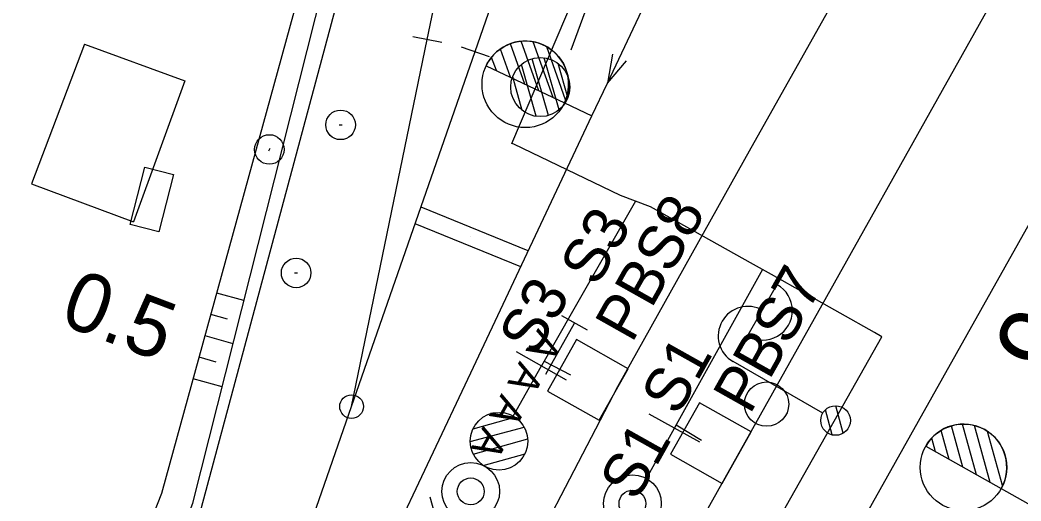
# Model space of a CAD drawing. Extents: x -781083 to -763634, y -1029516 to -1022695.
# Drawn here: x -765207.99 to -765174.13, y -1024229.83 to -1024213.57 of the extents above; entities that cross this region are included whole.
import ezdxf

# ---------------------------------------------------------------- set-up
doc = ezdxf.new("R2010")
doc.units = 0
for name, color, linetype in [('Default', 7, 'Continuous'), ('PS_12-01-10_Kabelizace_nove_kabelizace', 7, 'Continuous'), ('PS_12-01-11_SZZ_Slany_nove_prvky', 7, 'Continuous'), ('PS_12-01-11_SZZ_Slany_nove_prvky_popis', 7, 'Continuous'), ('PS_12-01-11_SZZ_Slany_rusene_prvky', 7, 'Continuous'), ('PS_12-01-11_SZZ_Slany_rusene_prvky_popis', 7, 'Continuous'), ('Vnitřní kresba', 7, 'Continuous'), ('Vrstva 1', 7, 'Continuous'), ('Vrstva 2', 7, 'Continuous'), ('Vrstva 25', 7, 'Continuous'), ('Vrstva 28', 7, 'Continuous'), ('Vrstva 48', 7, 'Continuous'), ('Vrstva 49', 7, 'Continuous'), ('Vrstva 7', 7, 'Continuous')]:
    doc.layers.add(name, color=color, linetype=linetype)

# ---------------------------------------------------------------- blocks, each defined once
blk = doc.blocks.new('C669')
at = {"layer": 'Vrstva 25'}
for p, q in [((0, 5), (0, 40)), ((7, 40), (33, 40)), ((-4.78, -1.46), (1.44, 4.76)), ((-2.39, -4.37), (4.38, 2.4))]:
    blk.add_line(p, q, dxfattribs=at)
blk.add_circle((0, 0), 5, dxfattribs=at)
for centre, start, end in [((10, 40), 0, 180), ((20, 39.88), 179.2974, 0.7026)]:
    blk.add_arc(centre, 10, start, end, dxfattribs=at)
blk = doc.blocks.new('C202')
at = {"layer": 'Vrstva 25'}
blk.add_lwpolyline([(-10, -5), (-10, 5), (10, 5), (10, -5), (-10, -5)], dxfattribs=at)
blk = doc.blocks.new('C053_2')
at = {"layer": 'Vrstva 25'}
blk.add_line((-0.5, 0), (0.5, 0), dxfattribs=at)
blk.add_circle((0, 0), 5, dxfattribs=at)
blk = doc.blocks.new('C093_3')
at = {"layer": 'Vrstva 7'}
blk.add_line((-0.5, 0), (0.5, 0), dxfattribs=at)
blk.add_circle((0, 0), 5, dxfattribs=at)
blk = doc.blocks.new('C321')
at = {"layer": 'Vrstva 2'}
blk.add_lwpolyline([(9.66, 2.59), (0, 0), (9.66, -2.59)], dxfattribs=at)
blk = doc.blocks.new('C084_2')
at = {"layer": 'Vrstva 2'}
blk.add_line((0, 5), (0, -5), dxfattribs=at)
blk = doc.blocks.new('C083_1')
at = {"layer": 'Vrstva 2'}
blk.add_circle((0, 0), 4, dxfattribs=at)
blk = doc.blocks.new('C515_2')
at = {"layer": 'Vrstva 2'}
for p, q in [((-0.02, 35.76), (3.35, 39.13)), ((-0.02, 30.45), (7.16, 37.63)), ((-0.02, 25.15), (10.19, 35.36)), ((-0.03, 19.84), (12.53, 32.4)), ((-0.03, 14.54), (14.1, 28.67)), ((1.1, 10.37), (14.53, 23.79)), ((0, 10.29), (0, 0))]:
    blk.add_line(p, q, dxfattribs=at)
blk.add_lwpolyline([(0, 39.56), (0, 10.29)], dxfattribs=at)
blk.add_circle((0, 24.93), 14.64, dxfattribs=at)
blk.add_arc((0, 24.93), 14.63, 270.0191, 89.98, dxfattribs=at)
blk = doc.blocks.new('C515_4')
at = {"layer": 'Vrstva 2'}
for p, q in [((-0.02, 35.76), (3.35, 39.13)), ((-0.02, 30.45), (7.16, 37.63)), ((-0.02, 25.15), (10.19, 35.36)), ((-0.03, 19.84), (12.53, 32.4)), ((-0.03, 14.54), (14.1, 28.67)), ((1.1, 10.37), (14.53, 23.79)), ((0, 10.29), (0, 0))]:
    blk.add_line(p, q, dxfattribs=at)
blk.add_lwpolyline([(0, 39.56), (0, 10.29)], dxfattribs=at)
blk.add_circle((0, 24.92), 14.64, dxfattribs=at)
blk.add_arc((0, 24.92), 14.63, 270.0191, 89.98, dxfattribs=at)
blk = doc.blocks.new('POINT_DISPLAY')
at = {"layer": 'Default'}
blk.add_line((0, 0), (0, 0), dxfattribs=at)
blk = doc.blocks.new('C335')
at = {"layer": 'Vrstva 7'}
blk.add_blockref('POINT_DISPLAY', (0, 0), dxfattribs=at)
blk = doc.blocks.new('C513_20')
at = {"layer": 'Vrstva 7'}
blk.add_circle((0, 0), 7.5, dxfattribs=at)
blk = doc.blocks.new('C016_8')
at = {"layer": 'PS_12-01-11_SZZ_Slany_rusene_prvky'}
for p, q in [((0, 5), (0, -5)), ((19.8, 0), (0, 0))]:
    blk.add_line(p, q, dxfattribs=at)
blk = doc.blocks.new('SB11_6')
at = {"layer": 'PS_12-01-11_SZZ_Slany_nove_prvky'}
blk.add_lwpolyline([(-125.2, 185.1), (-223.2, 11.3), (-49, -86.9), (49, 86.9)], close=True, dxfattribs=at)
blk = doc.blocks.new('NS12_1')
at = {"layer": 'PS_12-01-11_SZZ_Slany_nove_prvky'}
for p, q in [((-10.61, 115.61), (-17, 122)), ((-14.95, 104.3), (0.71, 119.96)), ((10.61, 115.61), (17, 122)), ((-14.06, 99.88), (5.12, 119.06)), ((-13.82, 110.73), (-5.7, 118.86)), ((-12.24, 96.4), (8.61, 117.25)), ((-9.72, 93.62), (11.4, 114.74)), ((-6.52, 91.51), (13.48, 111.52)), ((-2.5, 90.23), (14.77, 107.5)), ((2.88, 90.31), (14.72, 102.15)), ((-10.61, 94.39), (-17, 88)), ((10.61, 94.39), (17, 88)), ((0.97, 59.97), (-14.97, 44.03)), ((8.42, 57.42), (-12.42, 36.58)), ((12.99, 52.49), (-7.8, 32.19)), ((14.97, 45.97), (-1, 30)), ((0, 30), (0, 0)), ((-15, 0), (15, 0))]:
    blk.add_line(p, q, dxfattribs=at)
for centre, radius in [((0, 135), 15), ((0, 105), 15), ((0, 75), 15), ((0, 75), 7), ((0, 45), 15)]:
    blk.add_circle(centre, radius, dxfattribs=at)
blk = doc.blocks.new('NS8')
at = {"layer": 'PS_12-01-11_SZZ_Slany_nove_prvky'}
for p, q in [((-10.61, 85.61), (-17, 92)), ((-14.92, 73.72), (1.27, 89.91)), ((-14.24, 79.71), (-4.75, 89.19)), ((-13.91, 69.42), (5.56, 88.89)), ((10.61, 85.61), (17, 92)), ((-11.99, 66.04), (8.96, 86.99)), ((-9.38, 63.35), (11.66, 84.39)), ((-6.1, 61.33), (13.69, 81.12)), ((-1.96, 60.16), (14.86, 76.98)), ((3.63, 60.45), (14.51, 71.33)), ((-10.61, 64.39), (-17, 58)), ((10.61, 64.39), (17, 58)), ((0, 30), (0, 0)), ((-15, 0), (15, 0))]:
    blk.add_line(p, q, dxfattribs=at)
for centre, radius in [((0, 105), 15), ((0, 75), 15), ((0, 45), 15), ((0, 45), 7)]:
    blk.add_circle(centre, radius, dxfattribs=at)
blk = doc.blocks.new('PZ2_2')
at = {"layer": 'PS_12-01-11_SZZ_Slany_nove_prvky'}
for p, q in [((-18.83, -0.14), (-23.82, 17.41)), ((-14.74, 0.11), (-20.2, 19.3)), ((-11.12, 2.04), (-16.13, 19.62)), ((-8.14, 6.18), (-11.41, 17.64)), ((-23.54, 1.82), (-26.79, 13.24))]:
    blk.add_line(p, q, dxfattribs=at)
blk.add_circle((-17.47, 9.73), 10, dxfattribs=at)

msp = doc.modelspace()

# ---------------------------------------------------------------- linework, layer by layer
at = {"layer": 'PS_12-01-10_Kabelizace_nove_kabelizace'}
for p, q in [((-765187.174, -1024219.69), (-765190.349, -1024225.261)), ((-765182.877, -1024222.007), (-765185.855, -1024227.362)), ((-765190.256, -1024225.098), (-765189.37, -1024225.561)), ((-765185.793, -1024227.252), (-765184.938, -1024227.77))]:
    msp.add_line(p, q, dxfattribs=at)
msp.add_lwpolyline([(-765187.778, -1024240.091), (-765178.835, -1024224.275), (-765179.085, -1024224.133), (-765182.574, -1024222.177), (-765183.179, -1024221.837), (-765186.668, -1024219.881), (-765187.68, -1024219.499), (-765191.287, -1024217.769), (-765191.359, -1024217.739), (-765182.417, -1024196.766), (-765166.811, -1024163.482)], dxfattribs=at)
at = {"layer": 'Vnitřní kresba'}
for p, q in [((-765205.81, -1024214.38), (-765207.6, -1024219.11)), ((-765205.81, -1024214.38), (-765202.41, -1024215.62)), ((-765202.41, -1024215.62), (-765204.15, -1024220.39)), ((-765207.6, -1024219.11), (-765204.15, -1024220.39))]:
    msp.add_line(p, q, dxfattribs=at)
at = {"layer": 'Vrstva 1'}
for points in [[(-765188.123, -1024215.705), (-765183.275, -1024205.436), (-765176.4, -1024194.792), (-765173.261, -1024189.785), (-765169.195, -1024182.942), (-765164.586, -1024174.885), (-765158.873, -1024164.755), (-765150.27, -1024149.435), (-765143.977, -1024138.227), (-765137.411, -1024126.534), (-765129.538, -1024112.519), (-765123.879, -1024102.438), (-765115.14, -1024086.868), (-765106.342, -1024071.201), (-765098.535, -1024057.295), (-765090.39, -1024042.796), (-765081.493, -1024026.948), (-765072.655, -1024011.193), (-765066.823, -1024000.8), (-765059.521, -1023987.798)], [(-765188.645, -1024216.807), (-765188.123, -1024215.705), (-765183.275, -1024205.436), (-765177.884, -1024194.018), (-765175.294, -1024188.539), (-765171.011, -1024179.395), (-765166.902, -1024170.85), (-765161.865, -1024161.015), (-765157.64, -1024153.172), (-765153.216, -1024145.159), (-765145.723, -1024131.826), (-765138.513, -1024118.992), (-765134.338, -1024111.53), (-765125.127, -1024095.069), (-765118.846, -1024083.871), (-765111.182, -1024070.221), (-765102.382, -1024054.5), (-765092.788, -1024037.408), (-765084.151, -1024022.024), (-765076.991, -1024009.249), (-765068.63, -1023994.356)], [(-765215.522, -1024287.533), (-765214.869, -1024286.147), (-765208.592, -1024272.488), (-765202.041, -1024257.278), (-765199.225, -1024250.55), (-765195.719, -1024242.277), (-765191.973, -1024234.063), (-765191.905, -1024233.922), (-765187.773, -1024225.954), (-765183.261, -1024217.887), (-765177.292, -1024207.279), (-765170.878, -1024195.834), (-765163.532, -1024182.764), (-765155.727, -1024168.863), (-765148.415, -1024155.812), (-765140.866, -1024142.346)], [(-765200.909, -1024238.522), (-765200.512, -1024237.363), (-765196.775, -1024226.639), (-765194.217, -1024214.221), (-765192.75, -1024207.206), (-765190.136, -1024194.92), (-765187.944, -1024184.628), (-765186.685, -1024178.691), (-765184.006, -1024166.028), (-765181.702, -1024155.329), (-765179.632, -1024145.998)], [(-765208.592, -1024272.488), (-765200.394, -1024258.001), (-765194.324, -1024247.14), (-765187.882, -1024235.72), (-765182.524, -1024226.176), (-765175.117, -1024212.969), (-765167.745, -1024199.837), (-765160.378, -1024186.68), (-765154.91, -1024176.911), (-765146.757, -1024162.404), (-765139.177, -1024148.91)], [(-765227.172, -1024323.332), (-765226.383, -1024321.987), (-765218.823, -1024308.994), (-765212.016, -1024293.682), (-765210.286, -1024289.72), (-765207.837, -1024284.198), (-765203.542, -1024274.997), (-765199.177, -1024266.185), (-765195.745, -1024259.62), (-765191.959, -1024252.744), (-765183.924, -1024238.408), (-765177.594, -1024227.134), (-765171.735, -1024216.696), (-765164.143, -1024203.205), (-765156.397, -1024189.358), (-765149.423, -1024176.961), (-765143.434, -1024166.31), (-765138.578, -1024157.675), (-765133.719, -1024149)], [(-765192.593, -1024214.636), (-765189.514, -1024205.768), (-765186.319, -1024196.582), (-765184.058, -1024190.088)], [(-765200.909, -1024238.522), (-765200.512, -1024237.363), (-765196.775, -1024226.639), (-765192.593, -1024214.636)], [(-765211.766, -1024269.927), (-765211.276, -1024268.47), (-765206.854, -1024255.717), (-765199.221, -1024239.235), (-765196.829, -1024234.152), (-765192.736, -1024225.492), (-765188.645, -1024216.807)]]:
    msp.add_lwpolyline(points, dxfattribs=at)
at = {"layer": 'Vrstva 2'}
msp.add_line((-765196.775, -1024226.639), (-765194.217, -1024214.221), dxfattribs=at)
for points in [[(-765188.645, -1024216.807), (-765188.123, -1024215.705), (-765183.275, -1024205.436), (-765177.884, -1024194.018)], [(-765200.909, -1024238.522), (-765200.512, -1024237.363), (-765196.775, -1024226.639), (-765192.593, -1024214.636)]]:
    msp.add_lwpolyline(points, dxfattribs=at)
at = {"layer": 'Vrstva 28'}
msp.add_lwpolyline([(-765204.008, -1024235.573), (-765201.849, -1024230.046), (-765196.522, -1024210.191), (-765188.801, -1024213.093), (-765189.354, -1024214.586)], dxfattribs=at)
at = {"layer": 'Vrstva 48'}
for p, q in [((-765200.415, -1024223.056), (-765201.335, -1024222.803)), ((-765200.973, -1024223.681), (-765201.533, -1024223.526)), ((-765200.782, -1024224.511), (-765201.732, -1024224.249)), ((-765201.352, -1024225.132), (-765201.931, -1024224.972)), ((-765201.149, -1024225.965), (-765202.13, -1024225.696))]:
    msp.add_line(p, q, dxfattribs=at)
at = {"layer": 'Vrstva 49'}
for points in [[(-765224.162, -1024291.367), (-765215.697, -1024267.565), (-765204.627, -1024236.377), (-765202.143, -1024229.903), (-765195.789, -1024204.722), (-765193.85, -1024193.807)], [(-765203.195, -1024229.565), (-765196.324, -1024204.593), (-765193.85, -1024193.807)], [(-765225.333, -1024290.918), (-765216.428, -1024267.329), (-765205.715, -1024235.987), (-765203.195, -1024229.565)]]:
    msp.add_lwpolyline(points, dxfattribs=at)
at = {"layer": 'Vrstva 7'}
for p, q in [((-765190.796, -1024221.373), (-765194.424, -1024219.891)), ((-765191.052, -1024221.916), (-765194.622, -1024220.458))]:
    msp.add_line(p, q, dxfattribs=at)

# ---------------------------------------------------------------- block references
at = {"layer": 'PS_12-01-11_SZZ_Slany_nove_prvky'}
for name, p, xscale, yscale in [('PZ2_2', (-765188.645, -1024216.807), 0.1, 0.10000000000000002), ('SB11_6', (-765187.914, -1024226.226), 0.010000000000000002, 0.010000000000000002), ('SB11_6', (-765183.753, -1024228.365), 0.010000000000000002, 0.010000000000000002)]:
    msp.add_blockref(name, p, dxfattribs=dict(at, xscale=xscale, yscale=yscale))
at = {"layer": 'PS_12-01-11_SZZ_Slany_nove_prvky', "xscale": 0.06499999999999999, "yscale": 0.06499999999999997}
for name, p, rotation in [('NS12_1', (-765190.349, -1024225.261), 150.58545510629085), ('NS8', (-765185.852, -1024227.364), 150.92209893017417)]:
    msp.add_blockref(name, p, dxfattribs=dict(at, rotation=rotation))
at = {"layer": 'PS_12-01-11_SZZ_Slany_rusene_prvky', "xscale": 0.09999999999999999, "yscale": 0.09999999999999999, "rotation": -119.28438102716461}
msp.add_blockref('C016_8', (-765189.23, -1024223.814), dxfattribs=at)
at = {"layer": 'Vrstva 2'}
for name, p, xscale, yscale, rotation in [('C515_2', (-765188.645, -1024216.807), 0.10000000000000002, 0.1, 64.65382406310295), ('C084_2', (-765194.217, -1024214.221), 0.1, 0.10000000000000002, 78.35870925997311), ('C084_2', (-765192.593, -1024214.636), 0.09999999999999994, 0.09999999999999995, 70.78961031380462), ('C321', (-765188.123, -1024215.705), 0.1, 0.09999999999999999, 64.72677839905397), ('C083_1', (-765196.775, -1024226.639), 0.09999999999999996, 0.09999999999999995, -109.21038962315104), ('C515_4', (-765173.904, -1024229.916), 0.1, 0.10000000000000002, 60.610138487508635)]:
    msp.add_blockref(name, p, dxfattribs=dict(at, xscale=xscale, yscale=yscale, rotation=rotation))
at = {"layer": 'Vrstva 25', "xscale": 0.1, "yscale": 0.10000000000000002}
for p in [(-765197.146, -1024217.113), (-765198.65, -1024222.12)]:
    msp.add_blockref('C053_2', p, dxfattribs=at)
at = {"layer": 'Vrstva 25', "yscale": 0.10000000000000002}
for name, p, xscale, rotation in [('C202', (-765203.531, -1024219.634), 0.10000000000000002, 75.83802536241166), ('C669', (-765180.404, -1024227.11), 0.10000000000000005, 60.12442130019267)]:
    msp.add_blockref(name, p, dxfattribs=dict(at, xscale=xscale, rotation=rotation))
at = {"layer": 'Vrstva 7'}
for name, p, xscale, yscale, rotation in [('C093_3', (-765199.555, -1024217.945), 0.09999999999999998, 0.1, 61.52692531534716), ('C335', (-765192.769, -1024220.891), 0.10000000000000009, 0.10000000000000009, 90), ('C513_20', (-765182.737, -1024226.555), 0.09999999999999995, 0.09999999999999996, -119.30984687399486)]:
    msp.add_blockref(name, p, dxfattribs=dict(at, xscale=xscale, yscale=yscale, rotation=rotation))

# ---------------------------------------------------------------- texts
at = {"layer": 'PS_12-01-11_SZZ_Slany_nove_prvky_popis'}
for s, rotation, p in [('PBS8', 60.6062, (-765187.293, -1024224.522)), ('PBS7', 60.6062, (-765183.305, -1024226.941)), ('S3', 60.7156, (-765190.555, -1024224.996)), ('S1', 60.7156, (-765185.739, -1024226.995))]:
    msp.add_text(s, height=1.5, rotation=rotation, dxfattribs=at).set_placement(p)
at = {"layer": 'PS_12-01-11_SZZ_Slany_rusene_prvky'}
msp.add_text('  A A A A ', height=1, rotation=240.7156, dxfattribs=at).set_placement((-765190.102, -1024223.325))
at = {"layer": 'PS_12-01-11_SZZ_Slany_rusene_prvky_popis'}
for s, p in [('S3', (-765188.483, -1024222.626)), ('S1', (-765187.138, -1024229.883))]:
    msp.add_text(s, height=1.5, rotation=60.7156, dxfattribs=at).set_placement(p)
at = {"layer": 'Vrstva 2'}
msp.add_text('9', height=2.5, rotation=60.6101, dxfattribs=at).set_placement((-765172.987, -1024225.879))
at = {"layer": 'Vrstva 48'}
msp.add_text('0.5', height=2, rotation=339.2852, dxfattribs=at).set_placement((-765206.709, -1024223.819))

doc.saveas('drawing.dxf')
